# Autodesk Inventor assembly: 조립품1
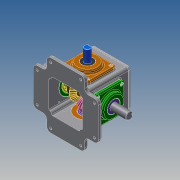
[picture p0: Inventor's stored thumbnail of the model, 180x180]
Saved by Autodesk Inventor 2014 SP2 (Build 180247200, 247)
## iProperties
Created: 2019-12
Part Number: 조립품1
Document SubType Name: Assembly
Designer: kb542-10
Mass: 4194.65 g
Surface Area: 3365.11 cm^2
Volume: 1062.39 cm^3
Density: 3.94832 g/cm^3
Author: kb542-10
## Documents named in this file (16)
- C:\Users\kb542-10\Desktop\391204V1038\답안조립품.iam
- C:\Users\kb542-10\Desktop\391204V1038\본체.ipt
- C:\Users\kb542-10\Desktop\391204V1038\개스킷.ipt
- C:\Users\kb542-10\Desktop\391204V1038\메인베벨기어.ipt
- C:\Users\kb542-10\Desktop\391204V1038\메인축.ipt
- C:\Users\kb542-10\Desktop\391204V1038\메인커버.ipt
- C:\Users\kb542-10\Desktop\391204V1038\베어링 6203.ipt
- C:\Users\kb542-10\Desktop\391204V1038\베어링 6204.ipt
- C:\Users\kb542-10\Desktop\391204V1038\볼트 M4.ipt
- C:\Users\kb542-10\Desktop\391204V1038\상부커버.ipt
- C:\Users\kb542-10\Desktop\391204V1038\서브베벨기어.ipt
- C:\Users\kb542-10\Desktop\391204V1038\서브축.ipt
- C:\Users\kb542-10\Desktop\391204V1038\서브커버.ipt
- C:\Users\kb542-10\Desktop\391204V1038\오일 실 17 32 8.ipt
- C:\Users\kb542-10\Desktop\391204V1038\오일 실 20 35 8.ipt
- C:\Users\kb542-10\Desktop\391204V1038\키 4x4.ipt
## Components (1 placed, 1 different names)
1. 개스킷:1
